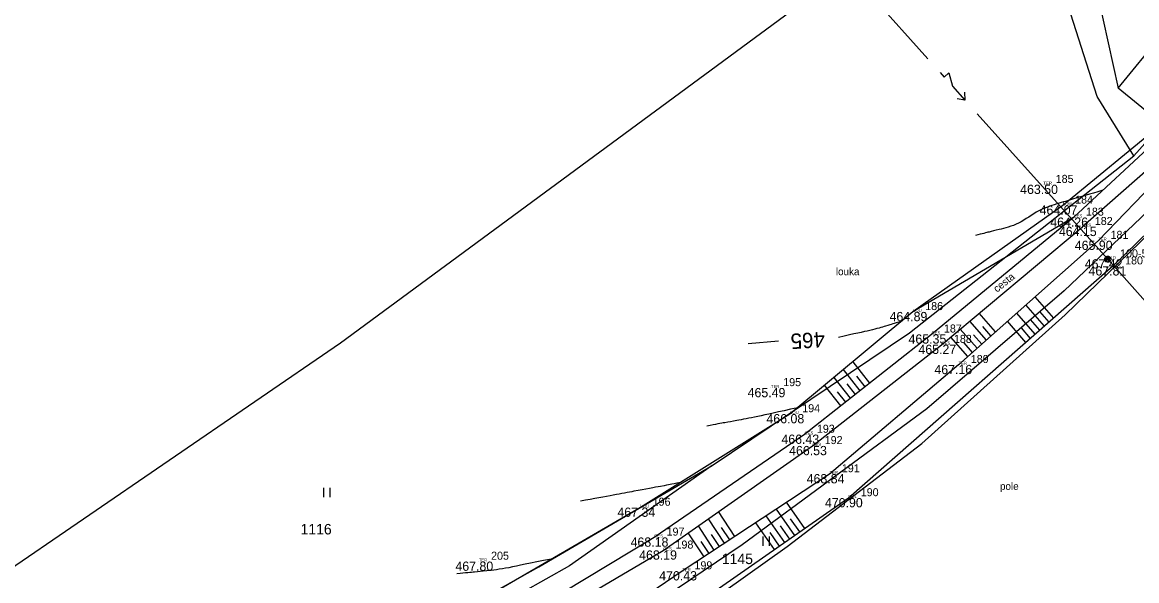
# Model space of a CAD drawing. Extents: x -604848 to -603227, y -1111879 to -1109838.
# Drawn here: x -603592.3 to -603411.4, y -1110449.9 to -1110359.3 of the extents above; entities that cross this region are included whole.
import ezdxf

# ---------------------------------------------------------------- set-up
doc = ezdxf.new("R2010")
doc.units = 0
for name, color, linetype in [('1', 7, 'Continuous'), ('10', 7, 'Continuous'), ('12', 7, 'Continuous'), ('14', 7, 'Continuous'), ('18', 7, 'Continuous'), ('19', 7, 'Continuous'), ('20', 7, 'Continuous'), ('23', 7, 'Continuous'), ('26', 7, 'Continuous'), ('4', 7, 'Continuous'), ('7', 7, 'Continuous'), ('8', 7, 'Continuous'), ('9', 7, 'Continuous'), ('Default', 7, 'Continuous')]:
    doc.layers.add(name, color=color, linetype=linetype)

# ---------------------------------------------------------------- blocks, each defined once
blk = doc.blocks.new('Z601')
at = {"layer": '26'}
for p, q in [((-0.5, 0.1), (-0.4, 0.3)), ((-0.5, -0.1), (-0.5, 0.1)), ((-0.4, 0.3), (-0.3, 0.4)), ((-0.3, 0.4), (-0.1, 0.5)), ((-0.3, 0.2), (-0.3, -0.2)), ((-0.1, 0.5), (0.1, 0.5)), ((-0.1, -0.3), (-0.1, 0.3)), ((-0.1, 0.3), (0.1, 0.3)), ((0.1, 0.5), (0.3, 0.4)), ((0.1, 0.3), (0.1, -0.3)), ((0.3, 0.4), (0.4, 0.3)), ((0.3, -0.2), (0.3, 0.2)), ((0.4, 0.3), (0.5, 0.1)), ((0.5, 0.1), (0.5, -0.1)), ((-0.4, -0.3), (-0.5, -0.1)), ((-0.3, -0.4), (-0.4, -0.3)), ((-0.3, -0.2), (-0.1, -0.3)), ((-0.1, -0.5), (-0.3, -0.4)), ((0.1, -0.5), (-0.1, -0.5)), ((0.1, -0.3), (0.3, -0.2)), ((0.3, -0.4), (0.1, -0.5)), ((0.4, -0.3), (0.3, -0.4)), ((0.5, -0.1), (0.4, -0.3))]:
    blk.add_line(p, q, dxfattribs=at)
blk = doc.blocks.new('Z3060')
at = {"layer": '23'}
for p, q in [((-0.5, 0), (-0.5, 1.5)), ((0.5, 1.5), (0.5, 0))]:
    blk.add_line(p, q, dxfattribs=at)
blk = doc.blocks.new('POINT_DISPLAY')
at = {"layer": 'Default'}
blk.add_line((0, 0), (0, 0), dxfattribs=at)
blk = doc.blocks.new('Z660')
at = {"layer": '12'}
for p, q in [((-3, 0), (-2, 0)), ((-2, 0), (-2, 1)), ((-2, 1), (0, 0)), ((0, 0), (3, 0)), ((2, 0.8), (3, 0)), ((3, 0), (2, -0.8))]:
    blk.add_line(p, q, dxfattribs=at)

msp = doc.modelspace()

# ---------------------------------------------------------------- linework, layer by layer
at = {"layer": '1'}
for p, q in [((-603432.14, -1110331.48), (-603540.65, -1110411.31)), ((-603418.57, -1110350.74), (-603414.36, -1110369.98)), ((-603417.76, -1110371.32), (-603423.67, -1110352.79)), ((-603414.36, -1110369.98), (-603407.29, -1110361.3)), ((-603411.84, -1110380.97), (-603417.76, -1110371.32)), ((-603407.24, -1110375.8), (-603414.36, -1110369.98)), ((-603422.97, -1110406.73), (-603387.2, -1110372.04)), ((-603411.84, -1110380.97), (-603407.24, -1110375.8)), ((-603448.25, -1110409.64), (-603411.84, -1110380.97)), ((-603402.9, -1110383.58), (-603423.16, -1110402.84)), ((-603423.16, -1110402.84), (-603445.43, -1110421.98)), ((-603446.27, -1110427.62), (-603422.97, -1110406.73)), ((-603480.28, -1110431.19), (-603448.25, -1110409.64)), ((-603540.65, -1110411.31), (-603658.23, -1110491.66)), ((-603445.43, -1110421.98), (-603475.45, -1110444.04)), ((-603468.11, -1110444.33), (-603446.27, -1110427.62)), ((-603508.42, -1110447.64), (-603480.28, -1110431.19)), ((-603480.28, -1110431.19), (-603503.49, -1110447.45)), ((-603475.45, -1110444.04), (-603501.2, -1110461.45)), ((-603486.47, -1110457.36), (-603468.11, -1110444.33)), ((-603587.44, -1110491.52), (-603508.42, -1110447.64)), ((-603503.49, -1110447.45), (-603584.38, -1110492.95))]:
    msp.add_line(p, q, dxfattribs=at)
at = {"layer": '10'}
for p, q in [((-603407.18, -1110375.71), (-603423.36, -1110388.99)), ((-603400.51, -1110384.49), (-603415.24, -1110398.86)), ((-603423.36, -1110388.99), (-603447.7, -1110406.27)), ((-603415.24, -1110398.86), (-603458.17, -1110436.47)), ((-603447.7, -1110406.27), (-603467.67, -1110422.84)), ((-603467.67, -1110422.84), (-603491.96, -1110438.01)), ((-603458.17, -1110436.47), (-603504.71, -1110468.89)), ((-603491.96, -1110438.01), (-603515.22, -1110451.51))]:
    msp.add_line(p, q, dxfattribs=at)
at = {"layer": '12'}
for p, q in [((-603457.28, -1110351.82), (-603445.26, -1110365.2)), ((-603437.24, -1110374.12), (-603416.05, -1110397.72)), ((-603416.05, -1110397.72), (-603384.15, -1110433.58))]:
    msp.add_line(p, q, dxfattribs=at)
at = {"layer": '4'}
for p, q in [((-603406.14, -1110376.57), (-603421.6, -1110390.95)), ((-603404.45, -1110378.64), (-603420.16, -1110392.46)), ((-603421.6, -1110390.95), (-603444.66, -1110409.91)), ((-603443.04, -1110411.59), (-603420.16, -1110392.46)), ((-603444.66, -1110409.91), (-603465.29, -1110426.17)), ((-603464.02, -1110428.01), (-603443.04, -1110411.59)), ((-603465.29, -1110426.17), (-603489.7, -1110442.86)), ((-603488.25, -1110444.96), (-603464.02, -1110428.01)), ((-603489.7, -1110442.86), (-603512.53, -1110456.56)), ((-603511.73, -1110458.73), (-603488.25, -1110444.96))]:
    msp.add_line(p, q, dxfattribs=at)
at = {"layer": '7'}
for p, q in [((-603417.6, -1110394.71), (-603395.25, -1110371.48)), ((-603421.6, -1110390.95), (-603447.7, -1110406.27)), ((-603417.6, -1110394.71), (-603440.3, -1110414.86)), ((-603469.51, -1110411.03), (-603474.43, -1110411.43)), ((-603440.3, -1110414.86), (-603461.24, -1110432.58)), ((-603454.68, -1110417.81), (-603457.41, -1110414.34)), ((-603457.82, -1110420.28), (-603460.49, -1110416.89)), ((-603456.25, -1110419.05), (-603458.95, -1110415.61)), ((-603455.46, -1110418.43), (-603456.82, -1110416.7)), ((-603459.39, -1110421.52), (-603462.03, -1110418.17)), ((-603457.03, -1110419.67), (-603458.38, -1110417.96)), ((-603458.6, -1110420.9), (-603459.93, -1110419.22)), ((-603461.24, -1110432.58), (-603485.17, -1110448.33)), ((-603485.17, -1110448.33), (-603508.11, -1110463.83))]:
    msp.add_line(p, q, dxfattribs=at)
for points in [[(-603416.85, -1110386.53), (-603419.15, -1110387.21), (-603421.45, -1110387.89), (-603423.75, -1110388.58), (-603427.34, -1110389.64), (-603430.44, -1110392.11), (-603434.08, -1110393), (-603435.23, -1110393.28), (-603436.38, -1110393.57), (-603437.54, -1110393.85)], [(-603449.5, -1110407.77), (-603450.27, -1110408), (-603451.04, -1110408.24), (-603451.82, -1110408.48), (-603454.45, -1110409.28), (-603457.13, -1110409.78), (-603459.78, -1110410.43)], [(-603466.36, -1110421.82), (-603469.77, -1110422.53), (-603473.17, -1110423.31), (-603476.58, -1110423.94), (-603478.11, -1110424.22), (-603479.64, -1110424.5), (-603481.16, -1110424.78)], [(-603485.43, -1110433.93), (-603486.31, -1110434.11), (-603487.19, -1110434.3), (-603488.08, -1110434.46), (-603492.62, -1110435.31), (-603497.16, -1110436.14), (-603501.7, -1110436.97)], [(-603506.4, -1110446.39), (-603510.01, -1110447.03), (-603513.58, -1110447.92), (-603517.23, -1110448.32), (-603518.74, -1110448.48), (-603520.25, -1110448.6), (-603521.77, -1110448.74)]]:
    msp.add_open_spline(points, degree=3, dxfattribs=at)
at = {"layer": '8'}
for p, q in [((-603424.83, -1110407.26), (-603427.85, -1110403.81)), ((-603426.33, -1110408.58), (-603429.35, -1110405.14)), ((-603435.77, -1110410.83), (-603438.48, -1110407.77)), ((-603434.27, -1110409.51), (-603436.95, -1110406.49)), ((-603429.34, -1110411.22), (-603432.34, -1110407.79)), ((-603427.84, -1110409.9), (-603430.84, -1110406.47)), ((-603427.09, -1110409.24), (-603428.59, -1110407.52)), ((-603425.58, -1110407.92), (-603427.09, -1110406.2)), ((-603437.26, -1110412.16), (-603440.02, -1110409.06)), ((-603435.02, -1110410.17), (-603436.36, -1110408.65)), ((-603428.59, -1110410.56), (-603430.09, -1110408.84)), ((-603438.76, -1110413.49), (-603441.55, -1110410.34)), ((-603438.01, -1110412.83), (-603439.4, -1110411.26)), ((-603436.51, -1110411.5), (-603437.88, -1110409.96)), ((-603476.61, -1110442.7), (-603479.26, -1110438.67)), ((-603466.88, -1110442.54), (-603469.87, -1110438.26)), ((-603465.24, -1110441.4), (-603468.2, -1110437.16)), ((-603478.28, -1110443.8), (-603480.9, -1110439.82)), ((-603470.16, -1110444.83), (-603473.21, -1110440.46)), ((-603468.52, -1110443.68), (-603471.54, -1110439.36)), ((-603466.06, -1110441.97), (-603467.55, -1110439.84)), ((-603481.62, -1110446), (-603484.18, -1110442.11)), ((-603479.95, -1110444.9), (-603482.54, -1110440.96)), ((-603477.45, -1110443.25), (-603478.76, -1110441.24)), ((-603469.34, -1110444.25), (-603470.86, -1110442.08)), ((-603467.7, -1110443.11), (-603469.2, -1110440.96)), ((-603480.79, -1110445.45), (-603482.07, -1110443.49)), ((-603479.12, -1110444.35), (-603480.42, -1110442.37))]:
    msp.add_line(p, q, dxfattribs=at)

# ---------------------------------------------------------------- block references
at = {"layer": '12', "xscale": 0.9999960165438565, "yscale": 0.9999960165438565, "rotation": -48.06813727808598}
msp.add_blockref('Z660', (-603441.26, -1110369.66), dxfattribs=at)
at = {"layer": '18'}
for p in [(-603426.51, -1110385.63), (-603423.36, -1110388.99), (-603421.6, -1110390.95), (-603420.16, -1110392.46), (-603417.6, -1110394.71), (-603416.05, -1110397.72), (-603415.24, -1110398.86), (-603447.7, -1110406.27), (-603444.66, -1110409.91), (-603443.04, -1110411.59), (-603440.3, -1110414.86), (-603470.76, -1110418.61), (-603467.67, -1110422.84), (-603465.29, -1110426.17), (-603464.02, -1110428.01), (-603461.24, -1110432.58), (-603458.17, -1110436.47), (-603491.96, -1110438.01), (-603489.7, -1110442.86), (-603488.25, -1110444.96), (-603518.2, -1110446.77), (-603485.17, -1110448.33)]:
    msp.add_blockref('POINT_DISPLAY', p, dxfattribs=at)
at = {"layer": '23'}
for p in [(-603542.87, -1110436.3), (-603471.53, -1110444.22)]:
    msp.add_blockref('Z3060', p, dxfattribs=at)
at = {"layer": '26'}
msp.add_blockref('Z601', (-603416.05, -1110397.72), dxfattribs=at)

# ---------------------------------------------------------------- texts
at = {"layer": '14'}
for s, p in [('1116', (-603547.14, -1110442.37)), ('1145', (-603478.73, -1110447.18))]:
    msp.add_text(s, height=1.7, dxfattribs=at).set_placement(p)
at = {"layer": '18'}
for s, p in [('TER', (-603426.51, -1110385.63)), ('LOU', (-603423.36, -1110388.99)), ('CES', (-603421.6, -1110390.95)), ('CES', (-603420.16, -1110392.46)), ('TER', (-603417.6, -1110394.71)), ('SLD', (-603416.05, -1110397.72)), ('POL', (-603415.24, -1110398.86)), ('LOU', (-603447.7, -1110406.27)), ('CES', (-603444.66, -1110409.91)), ('CES', (-603443.04, -1110411.59)), ('TER', (-603440.3, -1110414.86)), ('TER', (-603470.76, -1110418.61)), ('LOU', (-603467.67, -1110422.84)), ('CES', (-603465.29, -1110426.17)), ('CES', (-603464.02, -1110428.01)), ('TER', (-603461.24, -1110432.58)), ('POL', (-603458.17, -1110436.47)), ('LOU', (-603491.96, -1110438.01)), ('CES', (-603489.7, -1110442.86)), ('CES', (-603488.25, -1110444.96)), ('TER', (-603518.2, -1110446.77)), ('TER', (-603485.17, -1110448.33))]:
    msp.add_text(s, height=0.5, dxfattribs=at).set_placement(p)
at = {"layer": '19'}
for s, p in [('185', (-603424.51, -1110385.33)), ('184', (-603421.36, -1110388.69)), ('183', (-603419.6, -1110390.65)), ('182', (-603418.16, -1110392.16)), ('181', (-603415.6, -1110394.41)), ('100-585', (-603414.05, -1110397.42)), ('180', (-603413.24, -1110398.56)), ('186', (-603445.7, -1110405.97)), ('187', (-603442.66, -1110409.61)), ('188', (-603441.04, -1110411.29)), ('189', (-603438.3, -1110414.56)), ('195', (-603468.76, -1110418.31)), ('194', (-603465.67, -1110422.54)), ('193', (-603463.29, -1110425.87)), ('192', (-603462.02, -1110427.71)), ('191', (-603459.24, -1110432.28)), ('190', (-603456.17, -1110436.17)), ('196', (-603489.96, -1110437.71)), ('197', (-603487.7, -1110442.56)), ('198', (-603486.25, -1110444.66)), ('205', (-603516.2, -1110446.47)), ('199', (-603483.17, -1110448.03))]:
    msp.add_text(s, height=1.3, dxfattribs=at).set_placement(p)
at = {"layer": '20'}
for s, p in [('463.50 ', (-603430.28, -1110387.13)), ('464.07 ', (-603427.12, -1110390.49)), ('464.26 ', (-603425.39, -1110392.45)), ('464.15 ', (-603423.99, -1110393.96)), ('465.90 ', (-603421.41, -1110396.21)), ('467.42 ', (-603419.79, -1110399.22)), ('467.81 ', (-603419.18, -1110400.36)), ('464.89 ', (-603451.49, -1110407.77)), ('465.35 ', (-603448.41, -1110411.41)), ('465.27 ', (-603446.8, -1110413.09)), ('467.16 ', (-603444.21, -1110416.36)), ('465.49 ', (-603474.54, -1110420.11)), ('466.08 ', (-603471.48, -1110424.34)), ('466.43 ', (-603469.05, -1110427.67)), ('466.53 ', (-603467.8, -1110429.51)), ('468.84 ', (-603464.95, -1110434.08)), ('470.90 ', (-603461.98, -1110437.97)), ('467.34 ', (-603495.68, -1110439.51)), ('468.18 ', (-603493.54, -1110444.36)), ('468.19 ', (-603492.15, -1110446.46)), ('467.80 ', (-603521.99, -1110448.27)), ('470.43 ', (-603488.9, -1110449.83))]:
    msp.add_text(s, height=1.5, dxfattribs=at).set_placement(p)
at = {"layer": '7'}
msp.add_text('465', height=2.5, rotation=183.6, dxfattribs=at).set_placement((-603462.06, -1110409.47))
at = {"layer": '9'}
for s, p in [('louka', (-603460.21, -1110400.31)), ('pole', (-603433.56, -1110435.14))]:
    msp.add_text(s, height=1.2, dxfattribs=at).set_placement(p)
msp.add_text('cesta', height=1.2, rotation=38.7, dxfattribs=at).set_placement((-603434.04, -1110403.16))

doc.saveas('drawing.dxf')
